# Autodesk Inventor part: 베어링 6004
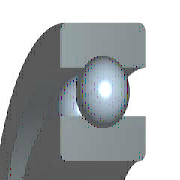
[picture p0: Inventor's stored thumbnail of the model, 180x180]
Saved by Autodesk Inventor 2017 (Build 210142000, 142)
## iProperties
IsCustomPart: 1
Created: 2012-02
Part Number: 베어링 6004
Material: 강철, 연강
Description: 깊은 그루브 볼 베어링
Document SubType Name: Modeling
Standard: KS B 2023
Designer: mduedu
Standards Organization: KS
Language: ko-KR
Size Designation: 6004 - 20 x 42 x 12
Categories: <MemberInstance><Categories><Category DisplayName="샤프트 부품" InternalName="7f7aeb1f-a693-4053-b835-cee3144e0d98" Mnemonic="SHFT"><Category DisplayName="베어링" Inter
Density: 7.85 g/cm^3
Appearance: 노란색
Mass: 68.2267 g
Surface Area: 70.0178 cm^2
Volume: 8.6913 cm^3
Author: mduedu
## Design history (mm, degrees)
sketch "스케치" dims "d0" = 5.72 (= -0.26 x WD + 0.26 x BD)
  geometry: L1 (3.14, 15.5)-(8.86, 15.5); L2 (6, 15.5)-(6, 12.64); L3 (6, 15.5)-(6, 18.36); L4 (3.875, 13.586)-(0, 13.586); L5 (0, 10)-(12, 10); L6 (3.875, 17.414)-(0, 17.414); L7 (0, 21)-(12, 21); L8 (12, 10)-(12, 13.586); L9 (8.125, 13.586)-(12, 13.586); L10 (8.125, 17.414)-(12, 17.414); L11 (12, 21)-(12, 17.414); L12 (-1.4, 0)-(8.4, 0) reference; L13 (0, -0.3)-(0, 5.3) reference
  constraints: 22 end point, 4 point on line, 2 collinear, 2 perpendicular, 2 symmetric about line, 1 midpoint, 1 parallel, 14 other
  dimensions: "d9" = 20 diameter of L5 L12 (= WD); "d11" = 42 diameter of L7 L12 (= BD); "d12" = 12 distance between parallel lines of L8 L13 (= KB); "d13" = 27.172 diameter of L9 L12 (= 0.326 x BD + 0.674 x WD)
revolve "본체" stored, may be unused: angle "d6" = 90 deg
revolve "볼" stored, may be unused: angle "d7" = 90 deg
pattern_circular "IDS_ARRAYBALL[SIMPL:T]" dims angle "d3" = 360 deg
body "Solid1"
fillet "모깎기1" dims "d1" = 0.6 (= KRS)
other parameters: "WD" = 20 [user parameter; used in 5 equation terms], "BD" = 42 [user parameter; used in 5 equation terms], "KB" = 12 [user parameter; used in 1 equation term], "KRS" = 0.6 [user parameter; used in 1 equation term], "d4" = 0, "d5" = 0, "d8" = 0, "d14" = 0, "d15" = 0, "BBA" = 0 [user parameter], "BC0" = 5000000 [user parameter], "BC" = 9360000 [user parameter], "BR" = 21 (= 0.5 x BD) [user parameter]
